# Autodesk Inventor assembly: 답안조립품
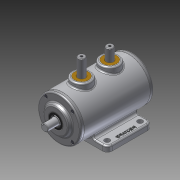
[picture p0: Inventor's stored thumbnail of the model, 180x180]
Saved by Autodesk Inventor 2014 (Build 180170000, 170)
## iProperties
Created: 2014-12
Part Number: 답안조립품
Document SubType Name: Assembly
Designer: Owner
Author: Owner
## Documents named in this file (10)
- C:\Users\Owner\Desktop\441223V1022\답안조립품.iam
- C:\Users\Owner\Desktop\441223V1022\1.본체.ipt
- C:\Users\Owner\Desktop\441223V1022\4.축.ipt
- C:\Users\Owner\Desktop\441223V1022\M4-소켓머리.ipt
- C:\Users\Owner\Desktop\441223V1022\뒷커버.ipt
- C:\Users\Owner\Desktop\441223V1022\베어링 6203.ipt
- C:\Users\Owner\Desktop\441223V1022\부시.ipt
- C:\Users\Owner\Desktop\441223V1022\슬라이더.ipt
- C:\Users\Owner\Desktop\441223V1022\앞커버.ipt
- C:\Users\Owner\Desktop\441223V1022\오일실.ipt
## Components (13 placed, 5 different names)
1. 1.본체:1
2. 4.축:1
3. 7-베어링 6203:1
4. 8-오일실:1
5. 7-베어링 6203:2
6. 9-M4-소켓머리:2
7. 9-M4-소켓머리:3
8. 9-M4-소켓머리:4
9. 9-M4-소켓머리:5
10. 9-M4-소켓머리:1
11. 9-M4-소켓머리:6
12. 9-M4-소켓머리:7
13. 9-M4-소켓머리:8
